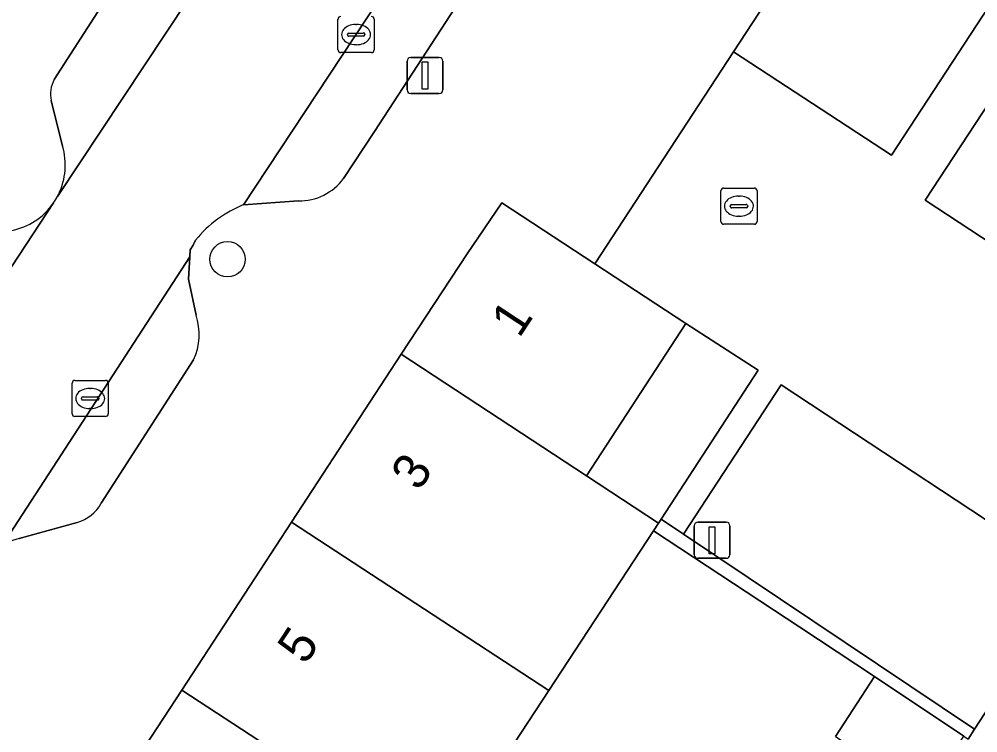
# Model space of a CAD drawing. Extents: x 159279 to 160377, y 384531 to 385888.
# Drawn here: x 159660.55 to 159687.08, y 385039.9 to 385059.66 of the extents above; entities that cross this region are included whole.
import ezdxf

# ---------------------------------------------------------------- set-up
doc = ezdxf.new("R2010")
doc.units = 0
for name, color, linetype in [('IMGEO_Boom', 7, 'Continuous'), ('IMGEO_Erf', 7, 'Continuous'), ('IMGEO_Groenvoorziening', 7, 'Continuous'), ('IMGEO_Hek', 7, 'Continuous'), ('IMGEO_Kolk', 7, 'Continuous'), ('IMGEO_Lichtmast', 7, 'Continuous'), ('IMGEO_Pand', 7, 'Continuous'), ('IMGEO_Pand_nummerreeks', 7, 'Continuous'), ('IMGEO_Parkeervlak_open', 7, 'Continuous'), ('IMGEO_Rijbaan_lokaal_open', 7, 'Continuous'), ('IMGEO_Voetpad_open', 7, 'Continuous')]:
    doc.layers.add(name, color=color, linetype=linetype)

msp = doc.modelspace()

# ---------------------------------------------------------------- linework, layer by layer
at = {"layer": 'IMGEO_Boom'}
msp.add_circle((159666.317, 385053.01), 0.489, dxfattribs=at)
at = {"layer": 'IMGEO_Erf'}
msp.add_lwpolyline([(159679.002, 385051.23), (159676.251, 385047.011), (159678.242, 385045.703), (159678.316, 385045.816), (159681.005, 385049.94)], close=True, dxfattribs=at)
msp.add_lwpolyline([(159683.14, 385039.801), (159684.227, 385041.461), (159682.154, 385042.826), (159678.104, 385045.493), (159675.21, 385041.075), (159672.168, 385036.431)], dxfattribs=at)
at = {"layer": 'IMGEO_Groenvoorziening'}
msp.add_lwpolyline([(159678.934, 385045.401), (159678.316, 385045.816), (159678.242, 385045.703), (159678.104, 385045.493), (159682.154, 385042.826), (159684.227, 385041.461), (159686.698, 385039.81), (159686.82, 385039.73), (159686.993, 385040.001)], close=True, dxfattribs=at)
at = {"layer": 'IMGEO_Hek'}
for points in [[(159676.479, 385052.885), (159680.322, 385058.747)], [(159679.002, 385051.23), (159681.005, 385049.94), (159678.316, 385045.816), (159678.242, 385045.703)]]:
    msp.add_lwpolyline(points, dxfattribs=at)
at = {"layer": 'IMGEO_Kolk'}
for p, q in [((159669.374, 385058.803), (159669.374, 385059.655)), ((159670.375, 385059.655), (159670.375, 385058.803)), ((159669.862, 385059.509), (159669.887, 385059.509)), ((159669.633, 385059.223), (159669.633, 385059.235)), ((159670.071, 385059.186), (159669.673, 385059.186)), ((159669.676, 385059.272), (159670.074, 385059.272)), ((159670.117, 385059.235), (159670.117, 385059.223)), ((159669.885, 385058.949), (159669.86, 385058.949)), ((159670.301, 385058.729), (159669.449, 385058.729)), ((159679.971, 385054.053), (159679.971, 385054.905)), ((159680.046, 385054.979), (159680.898, 385054.979)), ((159680.972, 385054.905), (159680.972, 385054.053)), ((159680.459, 385054.759), (159680.484, 385054.759)), ((159680.23, 385054.473), (159680.23, 385054.485)), ((159680.668, 385054.436), (159680.27, 385054.436)), ((159680.273, 385054.522), (159680.671, 385054.522)), ((159680.714, 385054.485), (159680.714, 385054.473)), ((159680.482, 385054.199), (159680.457, 385054.199)), ((159680.898, 385053.979), (159680.046, 385053.979)), ((159662.015, 385048.73), (159662.015, 385049.582)), ((159662.09, 385049.656), (159662.942, 385049.656)), ((159663.016, 385049.582), (159663.016, 385048.73)), ((159662.503, 385049.436), (159662.528, 385049.436)), ((159662.274, 385049.15), (159662.274, 385049.162)), ((159662.712, 385049.113), (159662.314, 385049.113)), ((159662.317, 385049.199), (159662.715, 385049.199)), ((159662.758, 385049.162), (159662.758, 385049.15)), ((159662.526, 385048.876), (159662.501, 385048.876)), ((159662.942, 385048.656), (159662.09, 385048.656))]:
    msp.add_line(p, q, dxfattribs=at)
for points in [[(159669.374, 385058.803), (159669.374, 385059.655)], [(159670.375, 385059.655), (159670.375, 385058.803)], [(159670.301, 385058.729), (159669.449, 385058.729)], [(159679.971, 385054.053), (159679.971, 385054.905)], [(159680.046, 385054.979), (159680.898, 385054.979)], [(159680.972, 385054.905), (159680.972, 385054.053)], [(159680.898, 385053.979), (159680.046, 385053.979)], [(159662.015, 385048.73), (159662.015, 385049.582)], [(159662.09, 385049.656), (159662.942, 385049.656)], [(159663.016, 385049.582), (159663.016, 385048.73)], [(159662.942, 385048.656), (159662.09, 385048.656)]]:
    msp.add_lwpolyline(points, dxfattribs=at)
for centre, radius, start, end in [((159669.451, 385059.653), 0.0765, 91.552, 178.448), ((159669.451, 385059.653), 0.0765, 91.552, 178.448), ((159670.299, 385059.653), 0.0765, 1.552, 88.448), ((159670.299, 385059.653), 0.0765, 1.552, 88.448), ((159669.673, 385059.232), 0.0403, 85.8775, 175.7526), ((159669.67, 385059.222), 0.0366, 178.938, 274.7102), ((159670.074, 385059.229), 0.043, 264.8664, 352.4533), ((159670.078, 385059.234), 0.0386, 1.7309, 96.639), ((159669.451, 385058.805), 0.0765, 181.552, 268.448), ((159669.451, 385058.805), 0.0765, 181.552, 268.448), ((159670.299, 385058.805), 0.0765, 271.552, 358.448), ((159670.299, 385058.805), 0.0765, 271.552, 358.448), ((159680.048, 385054.903), 0.0765, 91.552, 178.448), ((159680.048, 385054.903), 0.0765, 91.552, 178.448), ((159680.896, 385054.903), 0.0765, 1.552, 88.448), ((159680.896, 385054.903), 0.0765, 1.552, 88.448), ((159680.27, 385054.482), 0.0403, 85.8775, 175.7526), ((159680.267, 385054.472), 0.0366, 178.938, 274.7102), ((159680.671, 385054.479), 0.043, 264.8664, 352.4533), ((159680.675, 385054.484), 0.0386, 1.7309, 96.639), ((159680.048, 385054.055), 0.0765, 181.552, 268.448), ((159680.048, 385054.055), 0.0765, 181.552, 268.448), ((159680.896, 385054.055), 0.0765, 271.552, 358.448), ((159680.896, 385054.055), 0.0765, 271.552, 358.448), ((159662.092, 385049.58), 0.0765, 91.552, 178.448), ((159662.092, 385049.58), 0.0765, 91.552, 178.448), ((159662.94, 385049.58), 0.0765, 1.552, 88.448), ((159662.94, 385049.58), 0.0765, 1.552, 88.448), ((159662.314, 385049.159), 0.0403, 85.8775, 175.7526), ((159662.311, 385049.149), 0.0366, 178.938, 274.7102), ((159662.715, 385049.156), 0.043, 264.8664, 352.4533), ((159662.719, 385049.161), 0.0386, 1.7309, 96.639), ((159662.092, 385048.732), 0.0765, 181.552, 268.448), ((159662.092, 385048.732), 0.0765, 181.552, 268.448), ((159662.94, 385048.732), 0.0765, 271.552, 358.448), ((159662.94, 385048.732), 0.0765, 271.552, 358.448)]:
    msp.add_arc(centre, radius, start, end, dxfattribs=at)
for centre, major_axis, ratio, start_param, end_param in [((159669.861, 385059.229), (-0.387, 0.002), 0.722429, 4.712389, 7.853982), ((159669.886, 385059.229), (-0.39, 0.002), 0.717154, 1.570796, 4.712389), ((159680.458, 385054.479), (-0.387, 0.002), 0.722429, 4.712389, 7.853982), ((159680.483, 385054.479), (-0.39, 0.002), 0.717154, 1.570796, 4.712389), ((159662.502, 385049.156), (-0.387, 0.002), 0.722429, 4.712389, 7.853982), ((159662.527, 385049.156), (-0.39, 0.002), 0.717154, 1.570796, 4.712389)]:
    msp.add_ellipse(centre, major_axis=major_axis, ratio=ratio, start_param=start_param, end_param=end_param, dxfattribs=at)
at = {"layer": 'IMGEO_Lichtmast'}
for p, q in [((159671.387, 385058.595), (159672.177, 385058.595)), ((159672.177, 385058.595), (159671.387, 385058.595)), ((159671.287, 385057.695), (159671.287, 385058.495)), ((159671.287, 385058.495), (159671.287, 385057.695)), ((159672.277, 385058.495), (159672.277, 385057.695)), ((159672.277, 385057.695), (159672.277, 385058.495)), ((159672.177, 385057.595), (159671.387, 385057.595)), ((159671.387, 385057.595), (159672.177, 385057.595)), ((159679.231, 385044.832), (159679.231, 385045.632)), ((159679.231, 385045.632), (159679.231, 385044.832)), ((159679.331, 385045.732), (159680.121, 385045.732)), ((159680.121, 385045.732), (159679.331, 385045.732)), ((159680.221, 385045.632), (159680.221, 385044.832)), ((159680.221, 385044.832), (159680.221, 385045.632)), ((159680.121, 385044.732), (159679.331, 385044.732)), ((159679.331, 385044.732), (159680.121, 385044.732))]:
    msp.add_line(p, q, dxfattribs=at)
for points in [[(159671.707, 385058.47), (159671.857, 385058.47), (159671.857, 385057.72), (159671.707, 385057.72), (159671.707, 385058.47)], [(159679.651, 385045.607), (159679.801, 385045.607), (159679.801, 385044.857), (159679.651, 385044.857), (159679.651, 385045.607)]]:
    msp.add_lwpolyline(points, dxfattribs=at)
for centre, start, end in [((159671.387, 385058.495), 90, 180), ((159671.387, 385058.495), 90, 180), ((159672.177, 385058.495), 0, 90), ((159672.177, 385058.495), 360, 90), ((159671.387, 385057.695), 180, 270), ((159671.387, 385057.695), 180, 270), ((159672.177, 385057.695), 270, 0), ((159672.177, 385057.695), 270, 0), ((159679.331, 385045.632), 90, 180), ((159679.331, 385045.632), 90, 180), ((159680.121, 385045.632), 0, 90), ((159680.121, 385045.632), 360, 90), ((159679.331, 385044.832), 180, 270), ((159679.331, 385044.832), 180, 270), ((159680.121, 385044.832), 270, 0), ((159680.121, 385044.832), 270, 0)]:
    msp.add_arc(centre, 0.1, start, end, dxfattribs=at)
at = {"layer": 'IMGEO_Pand'}
for points in [[(159680.322, 385058.747), (159684.69, 385055.888), (159688.052, 385061.026), (159690.113, 385059.669), (159709.408, 385047.042), (159709.583, 385046.927), (159709.793, 385047.246), (159711.001, 385049.098), (159714.557, 385046.77), (159713.132, 385044.595), (159713.684, 385044.233), (159715.693, 385042.917), (159721.603, 385051.823), (159713.626, 385057.048), (159712.21, 385054.869), (159688.108, 385070.646)], [(159679.002, 385051.23), (159676.479, 385052.885), (159673.905, 385054.574), (159672.947, 385053.164), (159671.126, 385050.378), (159676.251, 385047.011)], [(159678.242, 385045.703), (159676.251, 385047.011), (159671.126, 385050.378), (159668.088, 385045.731), (159675.21, 385041.075), (159678.104, 385045.493)], [(159668.088, 385045.731), (159665.05, 385041.084), (159672.168, 385036.431), (159675.21, 385041.075)], [(159684.227, 385041.461), (159683.14, 385039.801), (159685.628, 385038.173), (159686.698, 385039.81)], [(159672.168, 385036.431), (159665.05, 385041.084), (159662.012, 385036.436), (159669.125, 385031.786), (159669.327, 385032.094), (159672.206, 385030.194), (159674.887, 385034.287), (159672.001, 385036.177)]]:
    msp.add_lwpolyline(points, close=True, dxfattribs=at)
at = {"layer": 'IMGEO_Parkeervlak_open'}
for points in [[(159678.672, 385072.552), (159666.763, 385054.52), (159668.277, 385054.625)], [(159669.529, 385055.245), (159670.38, 385056.55), (159678.941, 385069.686)], [(159661.644, 385054.815), (159661.627, 385054.782), (159661.61, 385054.75), (159671.239, 385069.281)], [(159668.145, 385068.26), (159661.521, 385057.984)], [(159661.44, 385057.401), (159661.75, 385056.137)], [(159652.518, 385040.886), (159661.5, 385054.568)], [(159665.446, 385051.466), (159665.234, 385052.455), (159665.274, 385053.079), (159659.919, 385044.859)], [(159662.822, 385046.254), (159665.379, 385050.221)], [(159660.55, 385045.282), (159662.152, 385045.722)]]:
    msp.add_lwpolyline(points, dxfattribs=at)
for points in [[(159704.251, 385048.484), (159688.391, 385058.861), (159685.629, 385054.646), (159701.487, 385044.232)], [(159678.934, 385045.401), (159686.993, 385040.001), (159689.734, 385044.198), (159681.638, 385049.533)]]:
    msp.add_lwpolyline(points, close=True, dxfattribs=at)
for centre, radius, start, end in [((159662.228, 385057.589), 0.81, 150.785, 193.3953), ((159659.983, 385055.613), 1.843, 334.3316, 16.4998), ((159668.302, 385056.149), 1.524, 269.0677, 323.6222), ((159659.979, 385055.614), 1.846, 281.27, 325.4695), ((159663.808, 385050.93), 1.724, 335.717, 18.1222), ((159661.829, 385046.816), 1.141, 286.4242, 330.477), ((159660.783, 385044.252), 1.056, 102.7644, 144.9086)]:
    msp.add_arc(centre, radius, start, end, dxfattribs=at)
at = {"layer": 'IMGEO_Rijbaan_lokaal_open'}
for points in [[(159666.763, 385054.52), (159678.672, 385072.552), (159679.644, 385074.024), (159675.984, 385076.419), (159674.162, 385073.664), (159671.239, 385069.281), (159661.61, 385054.75)], [(159688.052, 385061.026), (159684.69, 385055.888), (159680.322, 385058.747), (159676.479, 385052.885), (159679.002, 385051.23), (159681.005, 385049.94), (159678.316, 385045.816), (159678.934, 385045.401), (159681.638, 385049.533), (159689.734, 385044.198)], [(159661.5, 385054.568), (159652.518, 385040.886), (159646.935, 385031.761), (159644.447, 385027.972), (159642.414, 385024.877), (159640.705, 385022.275), (159640.084, 385021.339), (159639.191, 385019.992), (159639.064, 385019.858), (159638.986, 385019.776), (159641.952, 385017.841), (159642.182, 385018.227), (159645.527, 385023.106), (159651.154, 385031.619), (159659.378, 385044.063), (159659.919, 385044.859), (159665.274, 385053.079)], [(159665.274, 385053.079), (159665.287, 385053.272), (159665.364, 385053.403), (159665.432, 385053.539)]]:
    msp.add_lwpolyline(points, dxfattribs=at)
msp.add_lwpolyline([(159685.629, 385054.646), (159688.391, 385058.861), (159704.251, 385048.484), (159701.487, 385044.232)], close=True, dxfattribs=at)
for centre, radius, start, end in [((159660.375, 385055.372), 1.382, 324.4403, 333.2625), ((159667.981, 385051.475), 3.28, 111.7916, 140.9918)]:
    msp.add_arc(centre, radius, start, end, dxfattribs=at)
at = {"layer": 'IMGEO_Voetpad_open'}
for points in [[(159668.088, 385045.731), (159671.126, 385050.378), (159672.947, 385053.164), (159673.905, 385054.574), (159676.479, 385052.885), (159680.322, 385058.747), (159688.108, 385070.646), (159686.763, 385074.878), (159689.447, 385078.989), (159688.599, 385079.541), (159691.647, 385084.031), (159696.11, 385090.665), (159701.72, 385098.75)], [(159678.941, 385069.686), (159670.38, 385056.55), (159669.529, 385055.245)], [(159661.521, 385057.984), (159668.145, 385068.26)], [(159661.75, 385056.137), (159661.44, 385057.401)], [(159661.61, 385054.75), (159661.627, 385054.782), (159661.644, 385054.815)], [(159668.277, 385054.625), (159666.763, 385054.52)], [(159665.432, 385053.539), (159665.364, 385053.403), (159665.287, 385053.272), (159665.274, 385053.079), (159665.234, 385052.455), (159665.446, 385051.466)], [(159665.379, 385050.221), (159662.822, 385046.254)], [(159624.91, 384983.192), (159627.769, 384987.658), (159631.209, 384992.849), (159631.929, 384994.001), (159633.524, 384992.918), (159636.296, 384997.127), (159640.005, 385002.841), (159643.026, 385007.454), (159646.047, 385012.068), (159649.067, 385016.681), (159652.088, 385021.294), (159658.974, 385031.789), (159662.012, 385036.436), (159665.05, 385041.084), (159668.088, 385045.731)], [(159662.152, 385045.722), (159660.55, 385045.282)], [(159689.734, 385044.198), (159686.993, 385040.001), (159686.82, 385039.73)]]:
    msp.add_lwpolyline(points, dxfattribs=at)
for centre, radius, start, end in [((159662.228, 385057.589), 0.81, 150.785, 193.3953), ((159659.983, 385055.613), 1.843, 334.3316, 16.4998), ((159668.302, 385056.149), 1.524, 269.0677, 323.6222), ((159660.375, 385055.372), 1.382, 324.4403, 333.2625), ((159659.979, 385055.614), 1.846, 281.27, 325.4695), ((159667.981, 385051.475), 3.28, 111.7916, 140.9918), ((159663.808, 385050.93), 1.724, 335.717, 18.1222), ((159661.829, 385046.816), 1.141, 286.4242, 330.477), ((159660.783, 385044.252), 1.056, 102.7644, 144.9086)]:
    msp.add_arc(centre, radius, start, end, dxfattribs=at)

# ---------------------------------------------------------------- texts
at = {"layer": 'IMGEO_Pand_nummerreeks'}
for s, p in [('1', (159674.389, 385050.804)), ('3', (159671.617, 385046.563)), ('5', (159668.474, 385041.755))]:
    msp.add_text(s, height=1, rotation=56.6311, dxfattribs=at).set_placement(p)

doc.saveas('drawing.dxf')
